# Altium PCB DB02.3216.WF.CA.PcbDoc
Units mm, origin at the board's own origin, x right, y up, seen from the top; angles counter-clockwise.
Board outline 80.1 x 40.1 mm, 2 copper layers (Top Layer, Bottom Layer); 4 components, 2 nets, 13 pads, 292 vias.
Unrouted connection lines stored in the file: 56.
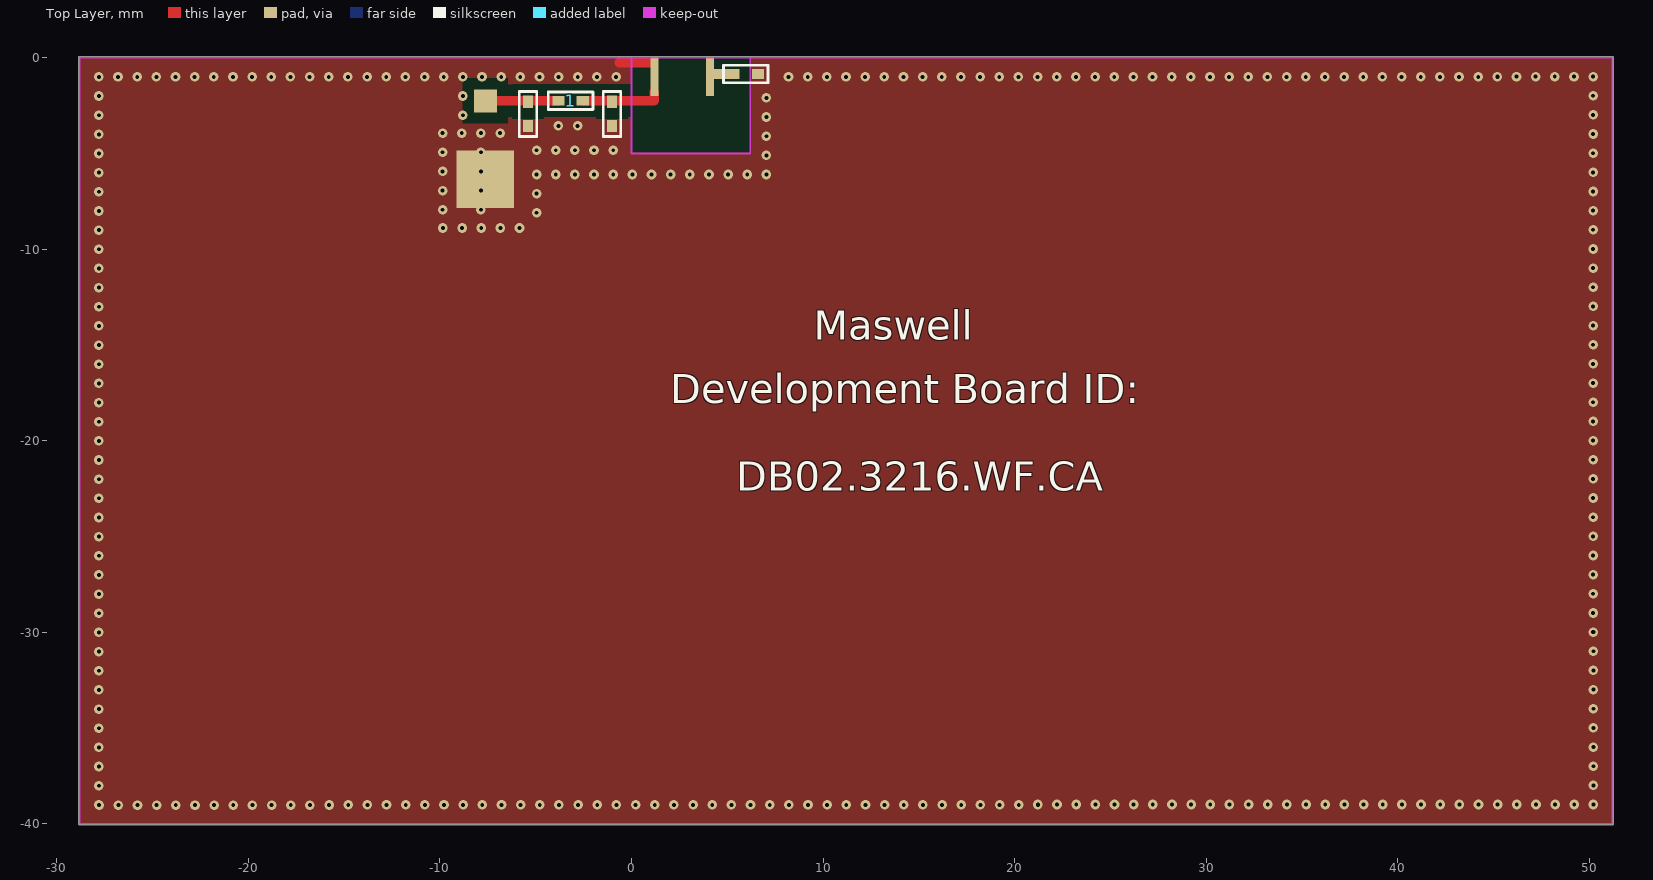
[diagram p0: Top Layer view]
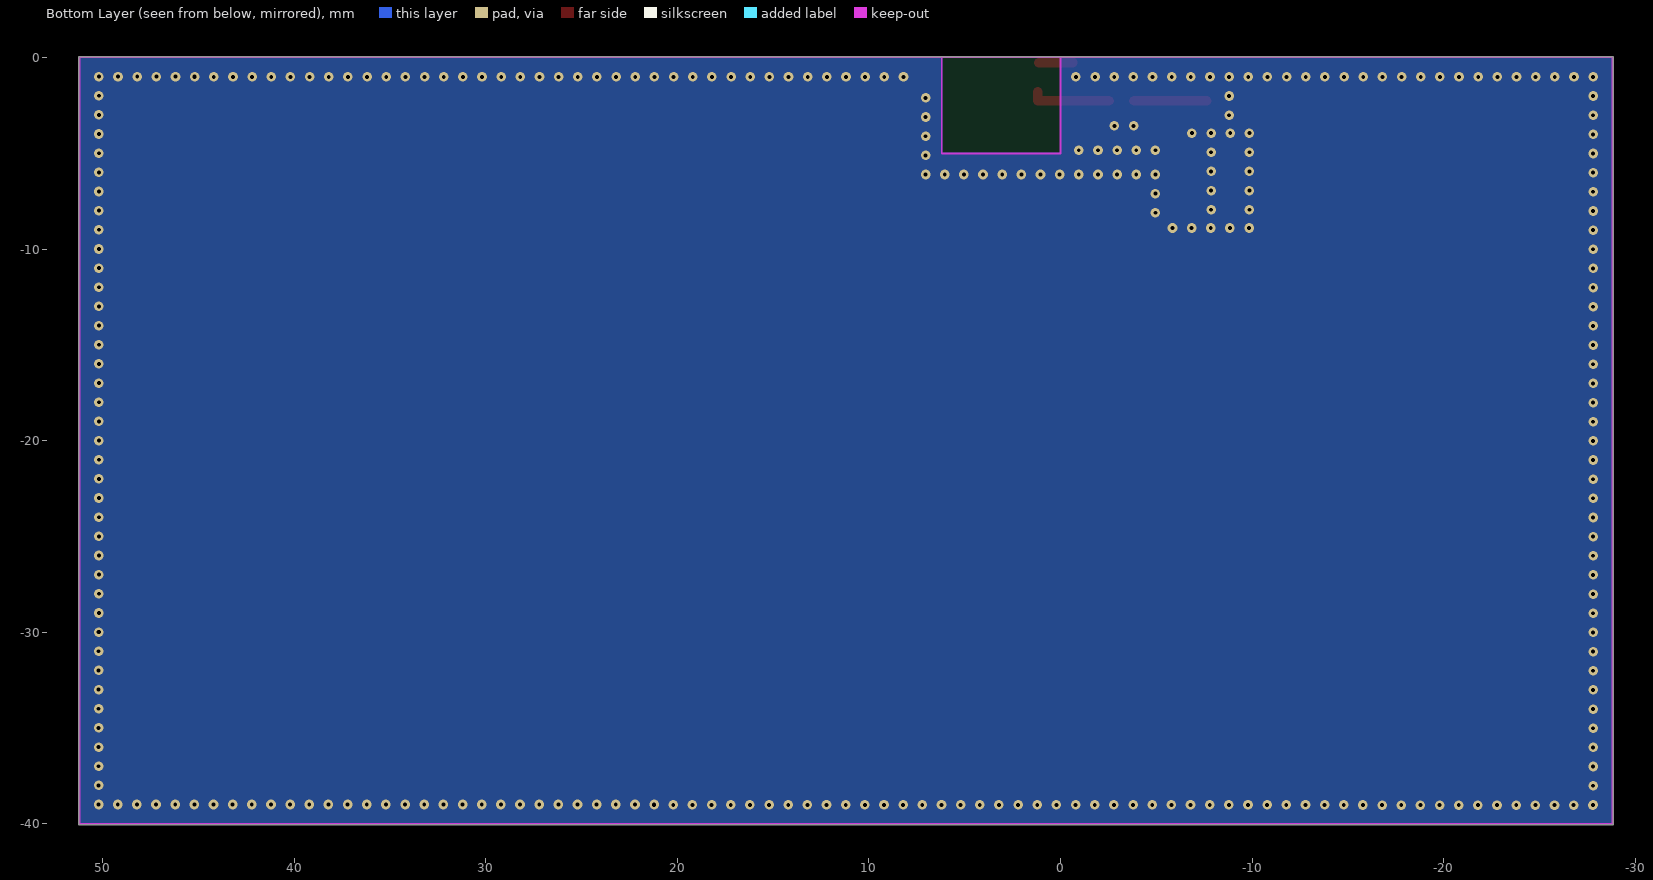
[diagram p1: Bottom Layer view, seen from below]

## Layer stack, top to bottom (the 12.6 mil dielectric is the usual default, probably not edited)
Top Solder: solder mask 0.0102, Solder Resist, Dk 3.5
Top Layer: signal copper 0.0356
Dielectric1: dielectric 0.32, FR-4, Dk 4.8
Bottom Layer: signal copper 0.0356
Bottom Solder: solder mask 0.0102, Solder Resist, Dk 3.5

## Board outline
-28.85,-40 ccw(c-28.8,-40) -28.8,-40.05 51.2,-40.05 ccw(c51.2,-40) 51.25,-40 51.25,0 ccw(c51.2,0) 51.2,0.05 -28.8,0.05 ccw(c-28.8,0) -28.85,0

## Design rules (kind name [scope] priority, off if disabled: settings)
Clearance [InNet('RF') vs (INPolygon)] p1: gap=0.6
PlaneConnect [All] p1: planeconnectstyle=Direct reliefexpansion=0.508 reliefentries=4 reliefconductorwidth=0.254 reliefairgap=0.254
PolygonConnect [All] p1: connectstyle=Direct reliefconductorwidth=0.254 reliefentries=4 polygonreliefangle="90 Angle" airgapwidth=0.254
RoutingVias [All] p1: holewidth=0.711 width=1.27 viastyle="Through Hole" minholewidth=0.711 minwidth=1.27 maxholewidth=0.711 maxwidth=1.27
SilkToSolderMaskClearance SilkscreenOverComponentPads [IsPad] p1: minsilkscreentomaskgap=0.254 clearancetoexposedcopper=TRUE
SolderMaskExpansion [All] p1: expansion=0.102
Width [All] p1: maxlimit=1 minlimit=1 preferedwidth=1
28 further rules are at their usual default settings.

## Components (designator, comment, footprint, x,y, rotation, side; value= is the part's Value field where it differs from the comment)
1 "" 0402s -2.54,-2.25 r180 top
? "" 0402s -5.4,-2.3 r270 top
? "" 0402s -1.016,-2.3 r270 top
? "" 0402s 6.604,-0.85 r180 top

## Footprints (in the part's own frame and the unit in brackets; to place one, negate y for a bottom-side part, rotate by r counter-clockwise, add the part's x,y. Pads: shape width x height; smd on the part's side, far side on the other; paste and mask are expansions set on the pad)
0402s [mil]
  rect 25x20 smd: 1(0,0) 2(50,0)
  silkscreen extent -21,-18 71,18

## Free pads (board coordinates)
  rect 3x3 smd mask+0.102: 0(-7.62,-6.35)
  rect 1.2x1.2 smd: 0(-7.62,-2.25)
  rect 0.4x2 smd mask+0.1: 0(1.2,-1) 0(4.1,-1)
  rect 1x0.5 smd mask+0: 0(4.8,-0.85)

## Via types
v1: diameter 0.5, hole 0.2, Top Layer to Bottom Layer, 292 vias

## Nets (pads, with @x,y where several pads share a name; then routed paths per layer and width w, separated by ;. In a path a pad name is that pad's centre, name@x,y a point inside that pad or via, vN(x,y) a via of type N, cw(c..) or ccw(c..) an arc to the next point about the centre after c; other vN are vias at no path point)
GND: ?.1@6.604,-0.85 ?.2@-1.016,-3.57 ?.2@-5.4,-3.57 pad.0@1.2,-1 pad.0@-7.62,-6.35
  other v1: -27.784,-39.016 -26.784,-39.016 -25.784,-39.016 -24.784,-39.016 -23.784,-39.016 -23.784,-39.016 -22.784,-39.016 -21.784,-39.016 -20.784,-39.016 -19.784,-39.016 -18.784,-39.016 -17.784,-39.016 -16.784,-39.016 -15.784,-39.016 -27.8,-39 -15.784,-39 -14.784,-39 -13.784,-39 -12.784,-39 -11.784,-39 -10.784,-39 -9.784,-39 -8.784,-39 -7.784,-39 -6.784,-39 -5.784,-39 -4.784,-39 -3.784,-39 -2.784,-39 -1.784,-39 -0.784,-39 0.216,-39 1.216,-39 2.216,-39 3.216,-39 4.216,-39 5.216,-39 6.216,-39 7.216,-39 8.216,-39 9.216,-39 10.216,-39 11.216,-39 12.216,-39 13.216,-39 13.216,-39 14.216,-39 15.216,-39 16.216,-39 17.216,-39 18.216,-39 19.216,-39 20.216,-39 21.216,-39 21.216,-38.984 22.216,-38.984 23.216,-38.984 24.216,-38.984 25.216,-38.984 26.216,-38.984 27.216,-38.984 28.216,-38.984 29.216,-38.984 30.216,-38.984 31.216,-38.984 32.216,-38.984 33.216,-38.984 34.216,-38.984 35.216,-38.984 36.216,-38.984 37.216,-38.984 38.216,-38.984 39.216,-38.984 40.216,-38.984 41.216,-38.984 42.216,-38.984 43.216,-38.984 44.216,-38.984 45.216,-38.984 46.216,-38.984 47.216,-38.984 48.216,-38.984 49.216,-38.984 50.216,-38.984 50.216,-38.984 -27.8,-38 50.216,-37.984 50.216,-37.984 -27.8,-37 50.216,-36.984 -27.8,-36 50.216,-35.984 -27.8,-35 50.216,-34.984 -27.8,-34 50.216,-33.984 -27.8,-33 50.216,-32.984 -27.8,-32 50.216,-31.984 -27.8,-31 50.216,-30.984 -27.8,-30 50.2,-29.984 50.216,-29.984 -27.8,-29 50.2,-28.984 -27.8,-28 50.2,-27.984 -27.8,-27 50.2,-26.984 -27.8,-26 50.2,-25.984 -27.8,-25 50.2,-24.984 -27.8,-24 50.2,-23.984 -27.8,-23 50.2,-22.984 -27.8,-22 50.2,-21.984 -27.8,-21 50.2,-20.984 -27.8,-20 50.2,-19.984 -27.8,-19 -27.8,-19 50.2,-18.984 -27.8,-18 50.2,-17.984 -27.8,-17 50.2,-16.984 -27.8,-16 50.2,-15.984 -27.8,-15 50.2,-14.984 -27.8,-14 50.2,-13.984 -27.8,-13 50.2,-12.984 -27.8,-12 50.2,-11.984 -27.8,-11 50.2,-10.984 -27.8,-10 50.2,-9.984 -27.8,-9 50.2,-8.984 -9.842,-8.89 -8.842,-8.89 -7.842,-8.89 -6.842,-8.89 -5.842,-8.89 -4.953,-8.096 -27.8,-8 50.2,-7.984 -9.858,-7.937 -7.858,-7.937 -4.953,-7.096 -27.8,-7 50.2,-6.984 -9.858,-6.937 -7.858,-6.937 -4.953,-6.096 -4.953,-6.096 -3.953,-6.096 -2.953,-6.096 -1.953,-6.096 -0.953,-6.096 0.047,-6.096 1.047,-6.096 2.047,-6.096 3.047,-6.096 3.047,-6.096 4.047,-6.096 5.047,-6.096 6.047,-6.096 7.047,-6.096 7.047,-6.096 -27.8,-6 50.2,-5.984 -9.858,-5.937 -7.858,-5.937 7.047,-5.096 -27.8,-5 50.2,-4.984 -9.858,-4.937 -7.858,-4.937 -4.953,-4.826 -3.953,-4.826 -2.953,-4.826 -1.953,-4.826 -0.953,-4.826 7.047,-4.096 -27.8,-4 50.2,-3.984 -9.858,-3.937 -9.858,-3.937 -8.858,-3.937 -7.858,-3.937 -7.858,-3.937 -6.858,-3.937 -3.81,-3.556 -2.81,-3.556 7.047,-3.096 -27.8,-3 -27.8,-3 -8.8,-3 50.2,-2.984 7.047,-2.096 -27.8,-2 -27.8,-2 -8.8,-2 50.2,-1.984 -27.8,-1 -27.8,-1 -27.8,-1 -27.8,-1 -26.8,-1 -25.8,-1 -24.8,-1 -23.8,-1 -22.8,-1 -21.8,-1 -20.8,-1 -19.8,-1 -18.8,-1 -17.8,-1 -16.8,-1 -15.8,-1 -14.8,-1 -13.8,-1 -12.8,-1 -11.8,-1 -10.8,-1 -9.8,-1 -8.8,-1 -8.8,-1 -7.8,-1 -6.8,-1 -5.8,-1 -4.8,-1 -3.8,-1 -2.8,-1 -1.8,-1 -0.8,-1 8.2,-1 9.2,-1 10.2,-1 11.2,-1 12.2,-1 13.2,-1 14.2,-1 15.2,-1 16.2,-1 16.2,-1 17.2,-1 18.2,-1 19.2,-1 20.2,-1 21.2,-1 22.2,-1 23.2,-1 24.2,-1 25.2,-1 26.2,-1 27.2,-1 28.2,-1 29.2,-1 30.2,-1 31.2,-1 32.2,-1 33.2,-1 34.2,-1 35.2,-1 36.2,-1 37.2,-1 38.2,-1 39.2,-1 40.2,-1 41.2,-1 42.2,-1 43.2,-1 44.2,-1 45.2,-1 45.2,-0.984 46.2,-0.984 47.2,-0.984 48.2,-0.984 49.2,-0.984 50.2,-0.984 50.2,-0.984
RF: 1.1 1.2 ?.1@-1.016,-2.3 ?.1@-5.4,-2.3 ?.2@5.334,-0.85 pad.0@-7.62,-2.25 | length 6.5
  Top Layer w0.5: pad.0@-7.62,-2.25 1.2 ; ?.1@-1.016,-2.25 1.2,-2.25 1.2,-1.778
copper on no net: | length 3.4
  Top Layer w0.254: -2.54,-2.25 -2.49,-2.3
  Top Layer w0.5: -2.54,-2.25 -1.016,-2.25 ; -0.635,-0.25 1.143,-0.254

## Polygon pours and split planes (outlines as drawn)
no net on Top Layer "Top Layer-No Net" (solid, pour order 0): -28.8,0 -0.004,0 -0.004,-8.128 -0.104,-8.255 -28.8,-8.255 -28.8,0
GND on Top Layer "Top Layer-No Net" (solid, pour order 2): 51.2,-4.953 51.2,-40 -28.759,-40 -28.8,-39.951 -28.8,-4.953 51.2,-4.953
no net on Top Layer "Top Layer-No Net" (solid, pour order 4): 6.2,0 51.2,0 51.2,-8.316 51.043,-8.445 6.2,-8.445 6.2,0
no net on Bottom Layer "Top Layer-No Net" (solid, pour order 6): 51.2,-4.953 51.2,-40 -28.759,-40 -28.8,-39.951 -28.8,-4.953 51.2,-4.953
no net on Bottom Layer "Top Layer-No Net" (solid, pour order 8): 6.177,0 51.177,0 51.177,-8.316 51.02,-8.445 6.177,-8.445 6.177,0
GND on Bottom Layer "Top Layer-No Net" (solid, pour order 10): -28.8,0 -0.004,0 -0.004,-8.128 -0.104,-8.255 -28.8,-8.255 -28.8,0

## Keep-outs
Keep-Out Layer:
  lines w0: -28.8,0 51.2,0
  lines w0.1: -28.8,0 -28.8,-40 51.2,-40 51.2,0 ; 0,0 0,-5 6.2,-5 6.2,0

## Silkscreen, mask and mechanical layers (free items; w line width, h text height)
Top Overlay:
  text "Maswell" at 9.525,-14.732 h1.52
  text "Development Board ID:" at 2.032,-18.034 h1.52
  text "DB02.3216.WF.CA" at 5.461,-22.606 h1.52
Mechanical 1:
  lines w0.1: -28.8,-20 -28.8,0 17.2,0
